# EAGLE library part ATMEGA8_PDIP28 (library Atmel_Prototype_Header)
ATMEL 8-bit AVR Microcontroller with 8K Bytes In-System Programmable Flash.
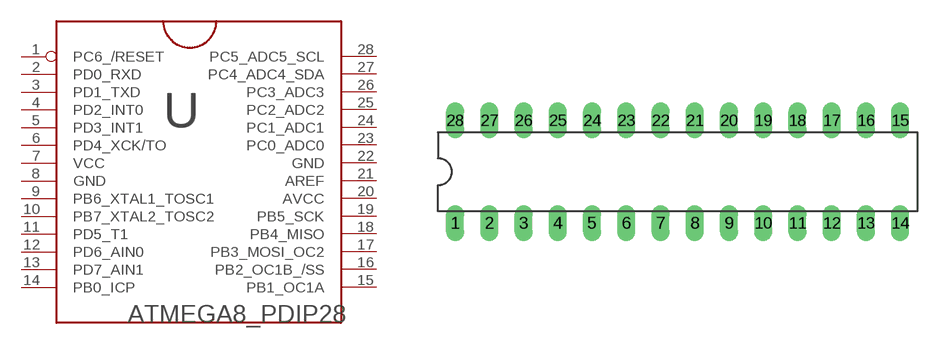
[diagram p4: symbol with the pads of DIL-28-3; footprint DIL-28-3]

Designator prefix U

## ATMEGA8_PDIP28_PDIP  [DIL-28-3]
1  PC6_/RESET
2  PD0_RXD
3  PD1_TXD
4  PD2_INT0
5  PD3_INT1
6  PD4_XCK/TO
7  VCC  pwr
8  GND  pwr
9  PB6_XTAL1_TOSC1
10  PB7_XTAL2_TOSC2
11  PD5_T1
12  PD6_AIN0
13  PD7_AIN1
14  PB0_ICP
15  PB1_OC1A
16  PB2_OC1B_/SS
17  PB3_MOSI_OC2
18  PB4_MISO
19  PB5_SCK
20  AVCC  pwr
21  AREF  pwr
22  GND  pwr
23  PC0_ADC0
24  PC1_ADC1
25  PC2_ADC2
26  PC3_ADC3
27  PC4_ADC4_SDA
28  PC5_ADC5_SCL

## Footprint DIL-28-3 (pad centres in mm)
drill 0.813 pad 1.321 long: 1 -16.51,-3.81; 2 -13.97,-3.81; 3 -11.43,-3.81; 4 -8.89,-3.81; 5 -6.35,-3.81; 6 -3.81,-3.81; 7 -1.27,-3.81; 8 1.27,-3.81; 9 3.81,-3.81; 10 6.35,-3.81; 11 8.89,-3.81; 12 11.43,-3.81; 13 13.97,-3.81; 14 16.51,-3.81; 15 16.51,3.81; 16 13.97,3.81; 17 11.43,3.81; 18 8.89,3.81; 19 6.35,3.81; 20 3.81,3.81; 21 1.27,3.81; 22 -1.27,3.81; 23 -3.81,3.81; 24 -6.35,3.81; 25 -8.89,3.81; 26 -11.43,3.81; 27 -13.97,3.81; 28 -16.51,3.81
